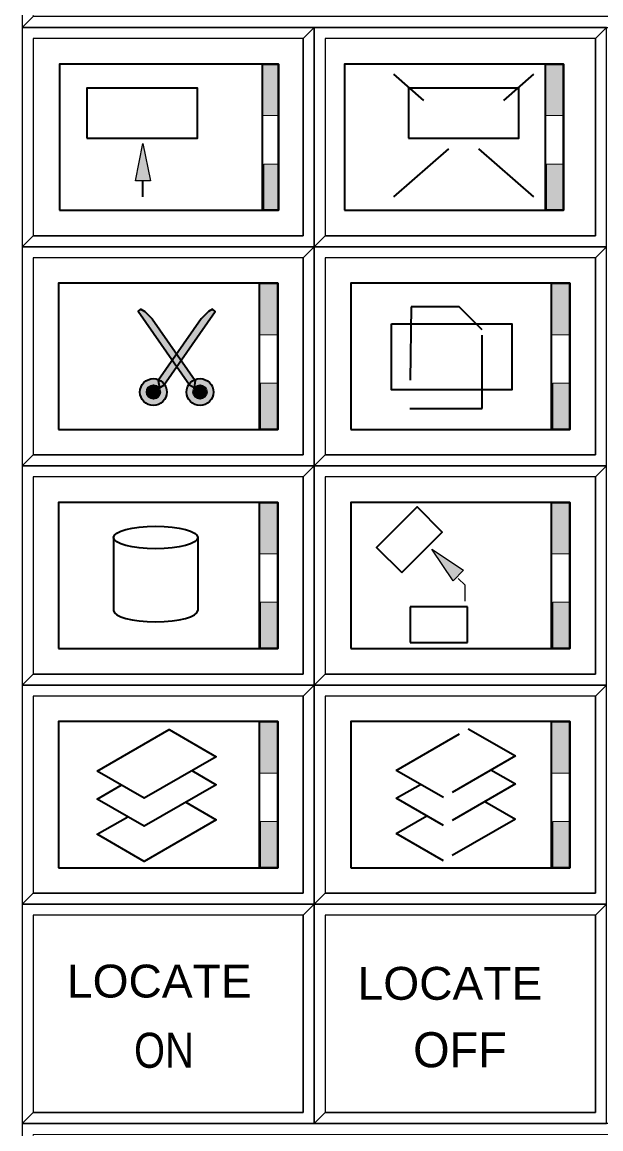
# Model space of a CAD drawing. Extents: x 95906.8 to 95923.6, y 90964.8 to 90972.8.
# Drawn here: x 95916.332 to 95917.125, y 90966.454 to 90967.969 of the extents above; entities that cross this region are included whole.
import ezdxf
from ezdxf.enums import TextEntityAlignment as Align

# ---------------------------------------------------------------- set-up
doc = ezdxf.new("R2010")
doc.units = 0
doc.header["$LTSCALE"] = 0.019
doc.linetypes.add('MEDIUM_DASHED', pattern=[4.5, 3, -1.5])
for name, color, linetype, lineweight in [('1', 7, 'Continuous', 25), ('11', 7, 'Continuous', 25), ('12', 7, 'Continuous', 25), ('2', 7, 'Continuous', 13), ('3', 7, 'Continuous', 25), ('6', 7, 'Continuous', 35)]:
    doc.layers.add(name, color=color, linetype=linetype, lineweight=lineweight)

msp = doc.modelspace()

# ---------------------------------------------------------------- hatches: boundary and pattern name
at = {"layer": '6'}
for points in [[(95916.6835, 90967.9117), (95916.6608, 90967.9117), (95916.6608, 90967.8412), (95916.6835, 90967.8412)], [(95917.0738, 90967.9117), (95917.048, 90967.9117), (95917.048, 90967.8412), (95917.0738, 90967.8412)], [(95916.4876, 90967.7519), (95916.4978, 90967.8031), (95916.508, 90967.7519)], [(95916.6632, 90967.7117), (95916.6835, 90967.7117), (95916.6835, 90967.775), (95916.6632, 90967.775)], [(95917.0504, 90967.7117), (95917.0738, 90967.7117), (95917.0738, 90967.775), (95917.0504, 90967.775)], [(95916.6823, 90967.6117), (95916.6565, 90967.6117), (95916.6565, 90967.5412), (95916.6823, 90967.5412)], [(95917.0823, 90967.6117), (95917.0565, 90967.6117), (95917.0565, 90967.5412), (95917.0823, 90967.5412)], [(95916.5617, 90967.4723), (95916.4912, 90967.573), (95916.4949, 90967.5765), (95916.5003, 90967.5732), (95916.5105, 90967.563), (95916.5694, 90967.4788), (95916.5677, 90967.4688)], [(95916.5263, 90967.4723), (95916.5968, 90967.573), (95916.5931, 90967.5765), (95916.5877, 90967.5732), (95916.5775, 90967.563), (95916.5186, 90967.4788), (95916.5203, 90967.4688)], [(95916.5305, 90967.4628, 1), (95916.4937, 90967.4628, 1)], [(95916.5575, 90967.4628, 1), (95916.5943, 90967.4628, 1)], [(95916.5213, 90967.4628, 1), (95916.5029, 90967.4628, 1)], [(95916.5667, 90967.4628, 1), (95916.5851, 90967.4628, 1)], [(95916.6589, 90967.4117), (95916.6823, 90967.4117), (95916.6823, 90967.475), (95916.6589, 90967.475)], [(95917.0589, 90967.4117), (95917.0823, 90967.4117), (95917.0823, 90967.475), (95917.0589, 90967.475)], [(95916.6823, 90967.3117), (95916.6565, 90967.3117), (95916.6565, 90967.2412), (95916.6823, 90967.2412)], [(95917.0823, 90967.3117), (95917.0565, 90967.3117), (95917.0565, 90967.2412), (95917.0823, 90967.2412)], [(95916.9224, 90967.2044), (95916.8934, 90967.2478), (95916.9368, 90967.2188)], [(95916.6589, 90967.1117), (95916.6823, 90967.1117), (95916.6823, 90967.175), (95916.6589, 90967.175)], [(95917.0589, 90967.1117), (95917.0823, 90967.1117), (95917.0823, 90967.175), (95917.0589, 90967.175)], [(95916.6823, 90967.0117), (95916.6565, 90967.0117), (95916.6565, 90966.9412), (95916.6823, 90966.9412)], [(95917.0823, 90967.0117), (95917.0565, 90967.0117), (95917.0565, 90966.9412), (95917.0823, 90966.9412)], [(95916.6589, 90966.8117), (95916.6823, 90966.8117), (95916.6823, 90966.875), (95916.6589, 90966.875)], [(95917.0589, 90966.8117), (95917.0823, 90966.8117), (95917.0823, 90966.875), (95917.0589, 90966.875)]]:
    msp.add_hatch(color=256, dxfattribs=at).paths.add_polyline_path(points)

# ---------------------------------------------------------------- linework, layer by layer
at = {"layer": '1'}
for points in [[(95916.3323, 90967.9617), (95917.9323, 90967.9617), (95917.9323, 90968.0617), (95916.3323, 90968.0617)], [(95916.3323, 90967.6617), (95916.7323, 90967.6617), (95916.7323, 90967.9617), (95916.3323, 90967.9617)], [(95916.7323, 90967.6617), (95917.1323, 90967.6617), (95917.1323, 90967.9617), (95916.7323, 90967.9617)], [(95916.3323, 90967.3617), (95916.7323, 90967.3617), (95916.7323, 90967.6617), (95916.3323, 90967.6617)], [(95916.7323, 90967.3617), (95917.1323, 90967.3617), (95917.1323, 90967.6617), (95916.7323, 90967.6617)], [(95916.3323, 90967.0617), (95916.7323, 90967.0617), (95916.7323, 90967.3617), (95916.3323, 90967.3617)], [(95916.7323, 90967.0617), (95917.1323, 90967.0617), (95917.1323, 90967.3617), (95916.7323, 90967.3617)], [(95916.3323, 90966.7617), (95916.7323, 90966.7617), (95916.7323, 90967.0617), (95916.3323, 90967.0617)], [(95916.7323, 90966.7617), (95917.1323, 90966.7617), (95917.1323, 90967.0617), (95916.7323, 90967.0617)], [(95916.3323, 90966.4617), (95916.7323, 90966.4617), (95916.7323, 90966.7617), (95916.3323, 90966.7617)], [(95916.7323, 90966.4617), (95917.1323, 90966.4617), (95917.1323, 90966.7617), (95916.7323, 90966.7617)], [(95916.3323, 90966.3617), (95917.9323, 90966.3617), (95917.9323, 90966.4617), (95916.3323, 90966.4617)]]:
    msp.add_lwpolyline(points, close=True, dxfattribs=at)
at = {"layer": '11'}
for points in [[(95916.7473, 90967.6767), (95917.1173, 90967.6767), (95917.1173, 90967.9467), (95916.7473, 90967.9467)], [(95916.3473, 90967.3767), (95916.7173, 90967.3767), (95916.7173, 90967.6467), (95916.3473, 90967.6467)], [(95916.7473, 90967.3767), (95917.1173, 90967.3767), (95917.1173, 90967.6467), (95916.7473, 90967.6467)], [(95916.3473, 90967.0767), (95916.7173, 90967.0767), (95916.7173, 90967.3467), (95916.3473, 90967.3467)], [(95916.7473, 90967.0767), (95917.1173, 90967.0767), (95917.1173, 90967.3467), (95916.7473, 90967.3467)], [(95916.3473, 90966.7767), (95916.7173, 90966.7767), (95916.7173, 90967.0467), (95916.3473, 90967.0467)], [(95916.7473, 90966.7767), (95917.1173, 90966.7767), (95917.1173, 90967.0467), (95916.7473, 90967.0467)], [(95916.3473, 90966.4767), (95916.7173, 90966.4767), (95916.7173, 90966.7467), (95916.3473, 90966.7467)], [(95916.7473, 90966.4767), (95917.1173, 90966.4767), (95917.1173, 90966.7467), (95916.7473, 90966.7467)]]:
    msp.add_lwpolyline(points, close=True, dxfattribs=at)
at = {"layer": '12'}
msp.add_lwpolyline([(95916.3473, 90967.6767), (95916.7173, 90967.6767), (95916.7173, 90967.9467), (95916.3473, 90967.9467)], close=True, dxfattribs=at)
at = {"layer": '2'}
for points in [[(95916.3323, 90968.0617), (95916.3323, 90967.9617), (95916.3473, 90967.9767), (95916.3473, 90968.0467), (95917.9173, 90968.0467), (95917.9323, 90968.0617)], [(95916.3323, 90967.9617), (95916.3323, 90967.6617), (95916.3473, 90967.6767), (95916.3473, 90967.9467), (95916.7173, 90967.9467), (95916.7323, 90967.9617)], [(95916.7323, 90967.9617), (95916.7323, 90967.6617), (95916.7473, 90967.6767), (95916.7473, 90967.9467), (95917.1173, 90967.9467), (95917.1323, 90967.9617)], [(95916.3323, 90967.6617), (95916.3323, 90967.3617), (95916.3473, 90967.3767), (95916.3473, 90967.6467), (95916.7173, 90967.6467), (95916.7323, 90967.6617)], [(95916.7323, 90967.6617), (95916.7323, 90967.3617), (95916.7473, 90967.3767), (95916.7473, 90967.6467), (95917.1173, 90967.6467), (95917.1323, 90967.6617)], [(95916.3323, 90967.3617), (95916.3323, 90967.0617), (95916.3473, 90967.0767), (95916.3473, 90967.3467), (95916.7173, 90967.3467), (95916.7323, 90967.3617)], [(95916.7323, 90967.3617), (95916.7323, 90967.0617), (95916.7473, 90967.0767), (95916.7473, 90967.3467), (95917.1173, 90967.3467), (95917.1323, 90967.3617)], [(95916.3323, 90967.0617), (95916.3323, 90966.7617), (95916.3473, 90966.7767), (95916.3473, 90967.0467), (95916.7173, 90967.0467), (95916.7323, 90967.0617)], [(95916.7323, 90967.0617), (95916.7323, 90966.7617), (95916.7473, 90966.7767), (95916.7473, 90967.0467), (95917.1173, 90967.0467), (95917.1323, 90967.0617)], [(95916.3323, 90966.7617), (95916.3323, 90966.4617), (95916.3473, 90966.4767), (95916.3473, 90966.7467), (95916.7173, 90966.7467), (95916.7323, 90966.7617)], [(95916.7323, 90966.7617), (95916.7323, 90966.4617), (95916.7473, 90966.4767), (95916.7473, 90966.7467), (95917.1173, 90966.7467), (95917.1323, 90966.7617)], [(95916.3323, 90966.4617), (95916.3323, 90966.3617), (95916.3473, 90966.3767), (95916.3473, 90966.4467), (95917.9173, 90966.4467), (95917.9323, 90966.4617)]]:
    msp.add_lwpolyline(points, close=True, dxfattribs=at)
at = {"layer": '3'}
for points in [[(95916.3323, 90967.9617), (95917.9323, 90967.9617), (95917.9323, 90968.0617), (95917.9173, 90968.0467), (95917.9173, 90967.9767), (95916.3473, 90967.9767)], [(95916.3323, 90967.6617), (95916.7323, 90967.6617), (95916.7323, 90967.9617), (95916.7173, 90967.9467), (95916.7173, 90967.6767), (95916.3473, 90967.6767)], [(95916.7323, 90967.6617), (95917.1323, 90967.6617), (95917.1323, 90967.9617), (95917.1173, 90967.9467), (95917.1173, 90967.6767), (95916.7473, 90967.6767)], [(95916.3323, 90967.3617), (95916.7323, 90967.3617), (95916.7323, 90967.6617), (95916.7173, 90967.6467), (95916.7173, 90967.3767), (95916.3473, 90967.3767)], [(95916.7323, 90967.3617), (95917.1323, 90967.3617), (95917.1323, 90967.6617), (95917.1173, 90967.6467), (95917.1173, 90967.3767), (95916.7473, 90967.3767)], [(95916.3323, 90967.0617), (95916.7323, 90967.0617), (95916.7323, 90967.3617), (95916.7173, 90967.3467), (95916.7173, 90967.0767), (95916.3473, 90967.0767)], [(95916.7323, 90967.0617), (95917.1323, 90967.0617), (95917.1323, 90967.3617), (95917.1173, 90967.3467), (95917.1173, 90967.0767), (95916.7473, 90967.0767)], [(95916.3323, 90966.7617), (95916.7323, 90966.7617), (95916.7323, 90967.0617), (95916.7173, 90967.0467), (95916.7173, 90966.7767), (95916.3473, 90966.7767)], [(95916.7323, 90966.7617), (95917.1323, 90966.7617), (95917.1323, 90967.0617), (95917.1173, 90967.0467), (95917.1173, 90966.7767), (95916.7473, 90966.7767)], [(95916.3323, 90966.4617), (95916.7323, 90966.4617), (95916.7323, 90966.7617), (95916.7173, 90966.7467), (95916.7173, 90966.4767), (95916.3473, 90966.4767)], [(95916.7323, 90966.4617), (95917.1323, 90966.4617), (95917.1323, 90966.7617), (95917.1173, 90966.7467), (95917.1173, 90966.4767), (95916.7473, 90966.4767)]]:
    msp.add_lwpolyline(points, close=True, dxfattribs=at)
at = {"layer": '6', "linetype": 'MEDIUM_DASHED'}
for p, q in [((95916.8414, 90967.73), (95917.033, 90967.8979)), ((95917.033, 90967.73), (95916.8414, 90967.8979))]:
    msp.add_line(p, q, dxfattribs=at)
at = {"layer": '6'}
for p, q in [((95916.4978, 90967.73), (95916.4978, 90967.7519)), ((95916.4575, 90967.2637), (95916.4575, 90967.1637)), ((95916.5729, 90967.2637), (95916.5729, 90967.1637))]:
    msp.add_line(p, q, dxfattribs=at)
for points in [[(95916.3835, 90967.7117), (95916.6835, 90967.7117), (95916.6835, 90967.9117), (95916.3835, 90967.9117)], [(95916.6835, 90967.7117), (95916.6616, 90967.7117), (95916.6616, 90967.9117), (95916.6835, 90967.9117)], [(95916.7738, 90967.7117), (95917.0738, 90967.7117), (95917.0738, 90967.9117), (95916.7738, 90967.9117)], [(95917.0738, 90967.7117), (95917.0488, 90967.7117), (95917.0488, 90967.9117), (95917.0738, 90967.9117)], [(95916.4209, 90967.8104), (95916.5723, 90967.8104), (95916.5723, 90967.879), (95916.4209, 90967.879)], [(95916.8612, 90967.8104), (95917.0126, 90967.8104), (95917.0126, 90967.879), (95916.8612, 90967.879)], [(95916.3823, 90967.4117), (95916.6823, 90967.4117), (95916.6823, 90967.6117), (95916.3823, 90967.6117)], [(95916.6823, 90967.4117), (95916.6573, 90967.4117), (95916.6573, 90967.6117), (95916.6823, 90967.6117)], [(95916.7823, 90967.4117), (95917.0823, 90967.4117), (95917.0823, 90967.6117), (95916.7823, 90967.6117)], [(95917.0823, 90967.4117), (95917.0573, 90967.4117), (95917.0573, 90967.6117), (95917.0823, 90967.6117)], [(95916.5617, 90967.4723), (95916.4912, 90967.573), (95916.4949, 90967.5765), (95916.5003, 90967.5732), (95916.5105, 90967.563), (95916.5694, 90967.4788), (95916.5677, 90967.4688)], [(95916.5263, 90967.4723), (95916.5968, 90967.573), (95916.5931, 90967.5765), (95916.5877, 90967.5732), (95916.5775, 90967.563), (95916.5186, 90967.4788), (95916.5203, 90967.4688)], [(95916.8379, 90967.5563), (95917.003, 90967.5563), (95917.003, 90967.466), (95916.8379, 90967.466)], [(95916.3823, 90967.1117), (95916.6823, 90967.1117), (95916.6823, 90967.3117), (95916.3823, 90967.3117)], [(95916.6823, 90967.1117), (95916.6573, 90967.1117), (95916.6573, 90967.3117), (95916.6823, 90967.3117)], [(95916.7823, 90967.1117), (95917.0823, 90967.1117), (95917.0823, 90967.3117), (95916.7823, 90967.3117)], [(95917.0823, 90967.1117), (95917.0573, 90967.1117), (95917.0573, 90967.3117), (95917.0823, 90967.3117)], [(95916.8521, 90967.2157), (95916.9076, 90967.2712), (95916.8731, 90967.3057), (95916.8176, 90967.2502)], [(95916.3823, 90966.8117), (95916.6823, 90966.8117), (95916.6823, 90967.0117), (95916.3823, 90967.0117)], [(95916.6823, 90966.8117), (95916.6573, 90966.8117), (95916.6573, 90967.0117), (95916.6823, 90967.0117)], [(95916.7823, 90966.8117), (95917.0823, 90966.8117), (95917.0823, 90967.0117), (95916.7823, 90967.0117)], [(95917.0823, 90966.8117), (95917.0573, 90966.8117), (95917.0573, 90967.0117), (95917.0823, 90967.0117)], [(95916.435, 90966.9438), (95916.5336, 90967.0008), (95916.5981, 90966.9636), (95916.4994, 90966.9067)]]:
    msp.add_lwpolyline(points, close=True, dxfattribs=at)
at = {"layer": '6', "lineweight": 13}
for points in [[(95916.6835, 90967.9117), (95916.6608, 90967.9117), (95916.6608, 90967.8412), (95916.6835, 90967.8412)], [(95917.0738, 90967.9117), (95917.048, 90967.9117), (95917.048, 90967.8412), (95917.0738, 90967.8412)], [(95916.6632, 90967.7117), (95916.6835, 90967.7117), (95916.6835, 90967.775), (95916.6632, 90967.775)], [(95917.0504, 90967.7117), (95917.0738, 90967.7117), (95917.0738, 90967.775), (95917.0504, 90967.775)], [(95916.6823, 90967.6117), (95916.6565, 90967.6117), (95916.6565, 90967.5412), (95916.6823, 90967.5412)], [(95917.0823, 90967.6117), (95917.0565, 90967.6117), (95917.0565, 90967.5412), (95917.0823, 90967.5412)], [(95916.6589, 90967.4117), (95916.6823, 90967.4117), (95916.6823, 90967.475), (95916.6589, 90967.475)], [(95917.0589, 90967.4117), (95917.0823, 90967.4117), (95917.0823, 90967.475), (95917.0589, 90967.475)], [(95916.6823, 90967.3117), (95916.6565, 90967.3117), (95916.6565, 90967.2412), (95916.6823, 90967.2412)], [(95917.0823, 90967.3117), (95917.0565, 90967.3117), (95917.0565, 90967.2412), (95917.0823, 90967.2412)], [(95916.6589, 90967.1117), (95916.6823, 90967.1117), (95916.6823, 90967.175), (95916.6589, 90967.175)], [(95917.0589, 90967.1117), (95917.0823, 90967.1117), (95917.0823, 90967.175), (95917.0589, 90967.175)], [(95916.6823, 90967.0117), (95916.6565, 90967.0117), (95916.6565, 90966.9412), (95916.6823, 90966.9412)], [(95917.0823, 90967.0117), (95917.0565, 90967.0117), (95917.0565, 90966.9412), (95917.0823, 90966.9412)], [(95916.6589, 90966.8117), (95916.6823, 90966.8117), (95916.6823, 90966.875), (95916.6589, 90966.875)], [(95917.0589, 90966.8117), (95917.0823, 90966.8117), (95917.0823, 90966.875), (95917.0589, 90966.875)]]:
    msp.add_lwpolyline(points, close=True, dxfattribs=at)
at = {"layer": '6', "lineweight": 25}
for points in [[(95916.4876, 90967.7519), (95916.4978, 90967.8031), (95916.508, 90967.7519)], [(95916.9224, 90967.2044), (95916.8934, 90967.2478), (95916.9368, 90967.2188)]]:
    msp.add_lwpolyline(points, close=True, dxfattribs=at)
at = {"layer": '6', "linetype": 'MEDIUM_DASHED'}
for points in [[(95916.8634, 90967.4405), (95916.9622, 90967.4405), (95916.9622, 90967.5478), (95916.9307, 90967.5793), (95916.8651, 90967.5793)], [(95916.8636, 90967.1199), (95916.9421, 90967.1199), (95916.9421, 90967.1687), (95916.8636, 90967.1687)], [(95916.8447, 90966.9449), (95916.9433, 90967.0019), (95917.0078, 90966.9647), (95916.9091, 90966.9078)]]:
    msp.add_lwpolyline(points, close=True, dxfattribs=at)
at = {"layer": '6', "lineweight": 25}
msp.add_lwpolyline([(95916.9389, 90967.1767), (95916.9389, 90967.1984), (95916.9294, 90967.2077)], dxfattribs=at)
at = {"layer": '6'}
for points in [[(95916.5645, 90966.9447), (95916.5981, 90966.9253), (95916.4994, 90966.8684), (95916.435, 90966.9056), (95916.468, 90966.9246)], [(95916.5563, 90966.9014), (95916.5981, 90966.8772), (95916.4994, 90966.8202), (95916.435, 90966.8574), (95916.4769, 90966.8814)]]:
    msp.add_lwpolyline(points, dxfattribs=at)
at = {"layer": '6', "linetype": 'MEDIUM_DASHED'}
for points in [[(95916.9742, 90966.9458), (95917.0078, 90966.9264), (95916.9091, 90966.8695), (95916.8447, 90966.9067), (95916.8777, 90966.9257)], [(95916.966, 90966.9025), (95917.0078, 90966.8783), (95916.9091, 90966.8213), (95916.8447, 90966.8585), (95916.8866, 90966.8825)]]:
    msp.add_lwpolyline(points, dxfattribs=at)
at = {"layer": '6'}
for centre, radius in [((95916.5121, 90967.4628), 0.0184), ((95916.5759, 90967.4628), 0.0184), ((95916.5121, 90967.4628), 0.00923), ((95916.5759, 90967.4628), 0.00923)]:
    msp.add_circle(centre, radius, dxfattribs=at)
msp.add_ellipse((95916.5152, 90967.2637), major_axis=(0.0577, 0), ratio=0.26816, dxfattribs=at)
msp.add_ellipse((95916.5152, 90967.1637), major_axis=(0.0577, 0), ratio=0.26816, start_param=3.141891, end_param=6.282846, dxfattribs=at)

# ---------------------------------------------------------------- texts
for s, height, width, p in [('LOCATE', 0.045, 1.05, (95916.5201, 90966.634)), ('LOCATE', 0.045, 1.05, (95916.9181, 90966.6309)), ('ON', 0.048, 0.85, (95916.5265, 90966.5378))]:
    msp.add_text(s, height=height, dxfattribs=dict(at, width=width)).set_placement(p, align=Align.CENTER)
msp.add_text('OFF', height=0.048, dxfattribs=at).set_placement((95916.9319, 90966.5385), align=Align.CENTER)

doc.saveas('drawing.dxf')
